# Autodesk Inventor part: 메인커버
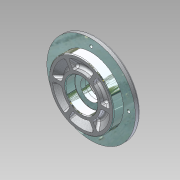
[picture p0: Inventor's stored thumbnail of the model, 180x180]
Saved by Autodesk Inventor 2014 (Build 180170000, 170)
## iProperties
Manager: KYOUNG IL JANG
Company: 한국ATC센터
Created: 2012-10
Part Number: 메인커버
Document SubType Name: Modeling
Density: 1 g/cm^3
Checked By: KYOUNG IL JANG
Vendor: CBT Solutions
Designer: KYOUNG IL JANG
Material: 일반
Appearance: _시험_알루미늄 표면거칠기
Author: KYOUNG IL JANG
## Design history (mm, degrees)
sketch "스케치1"
  geometry: L1 (0, 0)-(0, 28.5); L2 (0, 0)-(28.5, 0); L3 (28.5, 0)-(28.5, 4.726); L4 (28.5, 8)-(31.774, 8); L5 (32.966, 8)-(33.879, 7.234); L6 (42.5, 0)-(47.5, 0); L7 (47.5, 0)-(47.5, 14.5); L8 (47.5, 14.5)-(65, 14.5); L9 (65, 14.5)-(65, 22.5); L10 (65, 22.5)-(33.464, 22.5); L11 (33.464, 22.5)-(30, 28.5); L12 (30, 28.5)-(0, 28.5); L13 (28.5, 4.726)-(28.5, 8); L14 (31.774, 8)-(32.966, 8); L15 (33.879, 7.234)-(42.5, 0); L16 (23.5, 0)-(23.5, 14); L17 (23.5, 14)-(15, 14); L18 (15, 14)-(15, 20.5); L19 (15, 20.5)-(17.5, 20.5); L20 (17.5, 20.5)-(17.5, 28.5); A1 r 3.274 centre (31.774, 4.726) between (33.879, 7.234) and (28.5, 4.726)
  constraints: 40 end point, 11 parallel, 6 perpendicular, 6 tangent, 3 point on circle, 2 collinear, 2 point on line, 1 centre point, 1 vertical
  dimensions: "d1" = 130 diameter of L9 L1; "d2" = 95 diameter of L7 L1; "d3" = 57 diameter of L3 L1; "d4" = 5 distance of L6.start L6.end; "d5" = 14.5 distance between parallel lines of L8 L6; "d6" = 8 distance of L8.end L9.end; "d7" = 6 distance between parallel lines of L10 L12; "d8" = 8 distance of L2.end L4.start; "d9" = 140 deg angle of L6 L5; "d10" = 47 diameter of L16 L1; "d11" = 14 distance of L16.start L16.end; "d12" = 35 diameter of L20 L1; "d13" = 8 distance of L19.end L20.end; "d14" = 30 diameter of L18 L1; "d15" = 120 deg angle of L10 L11; "d16" = 60 diameter of L11.end L1
revolve "회전1" sketch "스케치1" stored, may be unused: angle "d17" = 90 deg
sketch "스케치2"
  geometry: L1 (28.5, 0)-(42.5, 0); 3 further points
  constraints: 2 end point, 2 horizontal alignment, 1 horizontal, 1 point on line, 2 other
feature "리브1" sketch "스케치2" dims "d18" = 5, "d19" = 1, "d20" = 0
fillet "모깎기1" dims "d21" = 3
fillet "모깎기2" dims "d25" = 3, "d26" = 0.3
chamfer "모따기1" distance "d27" = 1; stored, may be unused: second distance "d28" = 2, angle "d29" = 45 deg
sketch "스케치3"
  geometry: C1 r 2.067 at (55, 0) reference; C2 r 2.067 at (0, -55) reference; C3 r 2.067 at (-55, 0) reference; C4 r 2.067 at (0, 55) reference; 1 further point
hole "구멍1" sketch "스케치3" at (0, 55), (-55, 0), (0, -55), (55, 0) diameter "d30" = 4.5; stored, may be unused: countersink angle "d34" = 90 deg, drill point angle "d36" = 118 deg; dims "d31" = 6, "d32" = 8, "d33" = 4.4, "d35" = 8
node "솔리드1"
pattern_circular "원형 패턴1" dims angle "d23" = 360 deg
node "참조1"
node "참조2"
node "참조3"
node "참조4"
